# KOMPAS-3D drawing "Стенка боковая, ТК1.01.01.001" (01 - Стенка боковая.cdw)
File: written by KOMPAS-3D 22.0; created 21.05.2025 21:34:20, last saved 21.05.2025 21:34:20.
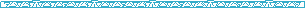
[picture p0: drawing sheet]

Sheet 1: A4, portrait

Document properties: Автор: user; Масса: 11.528421; Полное имя файла: ..\Стенка боковая.m3d

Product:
- Part/product: Стенка боковая  | designation ТК1.01.01.001
    Масса: 11.51708
- Part/product: Стенка боковая  | designation ТК1.01.01.001-01
    Масса: 11.528421

Title block, sheet 1: Наименование: Стенка боковая; designation: ТК1.01.01.001 - 01; Материал: Сталь 10 ГОСТ 1050-2013; Масса: 11,53; Количество листов документа: 1; Форматы листов документа: A4

Referenced files in D:\Работа\2025\5. Май\Задание №6 - Тележка для крыши\3Д\Тележка в сборе\Корпус тележки\: Стенка боковая.m3d
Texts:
  Без оформления
  ТК1.01.01.001
  ТК1.01.01.001-01 Стенка боковая
Dimensions and other numbers on the sheet: 1:1; 1; 11,53; 01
